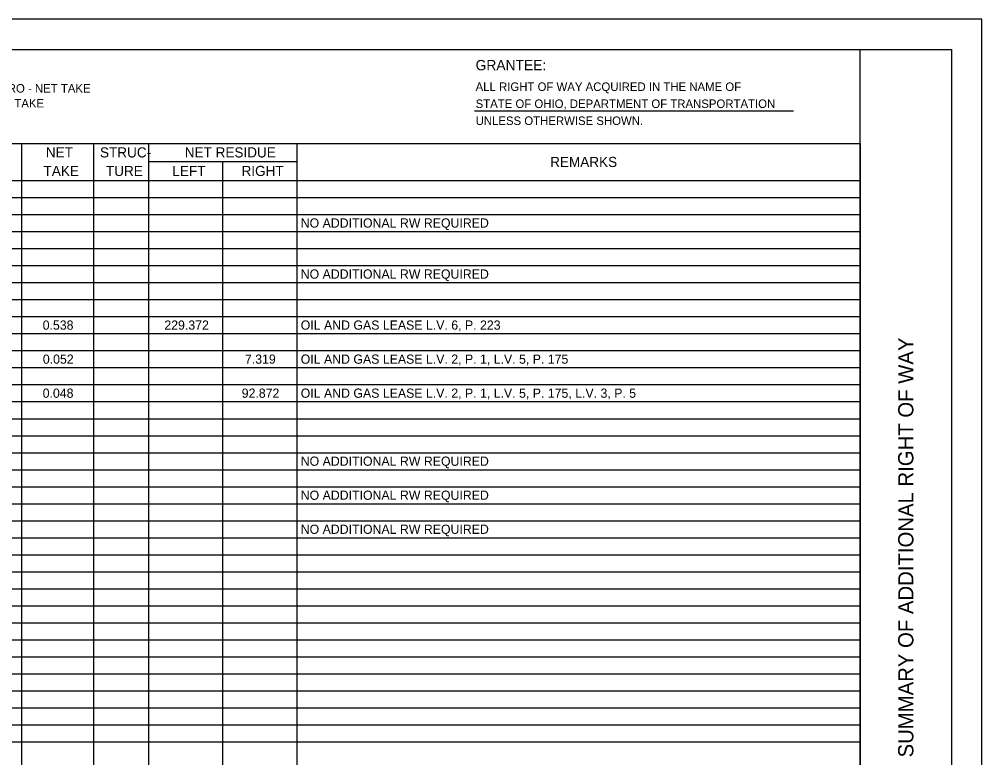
# Model space of a CAD drawing. Extents: x 0 to 34, y 0 to 22.
# Drawn here: x 18.16 to 34, y 9.85 to 22 of the extents above; entities that cross this region are included whole.
import ezdxf

# ---------------------------------------------------------------- set-up
doc = ezdxf.new("R2010")
doc.units = 0
for name, color, linetype in [('SH_Border', 7, 'Continuous'), ('SH_Cut_Line', 7, 'Continuous'), ('SH_Data', 7, 'Continuous'), ('SH_Text', 7, 'Continuous')]:
    doc.layers.add(name, color=color, linetype=linetype)

msp = doc.modelspace()

# ---------------------------------------------------------------- linework, layer by layer
at = {"layer": 'SH_Border'}
msp.add_line((32, 0.5), (32, 21.5), dxfattribs=at)
msp.add_lwpolyline([(1.5, 21.5), (33.5, 21.5), (33.5, 0.5), (1.5, 0.5)], close=True, dxfattribs=at)
at = {"layer": 'SH_Cut_Line'}
msp.add_lwpolyline([(0, 0), (34, 0), (34, 22), (0, 22)], close=True, dxfattribs=at)
at = {"layer": 'SH_Text'}
for p, q in [((25.651, 20.492), (30.9, 20.492)), ((1.5, 19.957), (32, 19.957)), ((18.199, 19.957), (18.199, 3.39)), ((19.385, 19.957), (19.385, 3.39)), ((20.291, 19.957), (20.291, 3.39)), ((22.728, 19.957), (22.728, 3.39)), ((32, 19.957), (32, 3.39)), ((20.291, 19.661), (22.728, 19.661)), ((21.509, 19.661), (21.509, 3.39)), ((1.5, 19.348), (32, 19.348)), ((1.5, 19.068), (32, 19.068)), ((1.5, 18.788), (32, 18.788)), ((1.5, 18.508), (32, 18.508)), ((1.5, 18.228), (32, 18.228)), ((1.5, 17.948), (32, 17.948)), ((1.5, 17.668), (32, 17.668)), ((1.5, 17.388), (32, 17.388)), ((1.5, 17.108), (32, 17.108)), ((1.5, 16.828), (32, 16.828)), ((1.5, 16.548), (32, 16.548)), ((1.5, 16.268), (32, 16.268)), ((1.5, 15.988), (32, 15.988)), ((1.5, 15.708), (32, 15.708)), ((1.5, 15.428), (32, 15.428)), ((1.5, 15.148), (32, 15.148)), ((1.5, 14.868), (32, 14.868)), ((1.5, 14.588), (32, 14.588)), ((1.5, 14.308), (32, 14.308)), ((1.5, 14.028), (32, 14.028)), ((1.5, 13.748), (32, 13.748)), ((1.5, 13.468), (32, 13.468)), ((1.5, 13.188), (32, 13.188)), ((1.5, 12.909), (32, 12.909)), ((1.5, 12.629), (32, 12.629)), ((1.5, 12.349), (32, 12.349)), ((1.5, 12.069), (32, 12.069)), ((1.5, 11.789), (32, 11.789)), ((1.5, 11.509), (32, 11.509)), ((1.5, 11.229), (32, 11.229)), ((1.5, 10.949), (32, 10.949)), ((1.5, 10.669), (32, 10.669)), ((1.5, 10.389), (32, 10.389)), ((1.5, 10.109), (32, 10.109))]:
    msp.add_line(p, q, dxfattribs=at)

# ---------------------------------------------------------------- texts
at = {"layer": 'SH_Data'}
msp.add_text('SUMMARY OF ADDITIONAL RIGHT OF WAY', height=0.25, rotation=90, dxfattribs=at).set_placement((32.875, 9.854))
at = {"layer": 'SH_Text'}
for s, height, p in [('GRANTEE:', 0.17, (25.672, 21.16)), ('NET RESIDUE = RECORD AREA - TOTAL PRO - NET TAKE', 0.14, (14.182, 20.793)), ('ALL RIGHT OF WAY ACQUIRED IN THE NAME OF', 0.14, (25.672, 20.82)), ('NET TAKE = GROSS TAKE - PRO IN TAKE', 0.14, (14.873, 20.548)), ('STATE OF OHIO, DEPARTMENT OF TRANSPORTATION', 0.14, (25.672, 20.54)), ('UNLESS OTHERWISE SHOWN.', 0.14, (25.672, 20.26)), ('NET', 0.1667, (18.601, 19.726)), ('STRUC-', 0.1667, (19.491, 19.726)), ('NET RESIDUE', 0.16666, (20.886, 19.726)), ('REMARKS', 0.1667, (26.898, 19.569)), ('TAKE', 0.1667, (18.562, 19.421)), ('TURE', 0.1667, (19.589, 19.421)), ('LEFT', 0.1667, (20.682, 19.421)), ('RIGHT', 0.1667, (21.82, 19.421)), ('NO ADDITIONAL RW REQUIRED', 0.15151, (22.794, 18.572)), ('NO ADDITIONAL RW REQUIRED', 0.15151, (22.794, 17.732)), ('0.538', 0.1515, (18.548, 16.892)), ('229.372', 0.1515, (20.55, 16.892)), ('OIL AND GAS LEASE L.V. 6, P. 223', 0.15151, (22.794, 16.892)), ('0.052', 0.1515, (18.551, 16.332)), ('7.319', 0.1515, (21.876, 16.332)), ('OIL AND GAS LEASE L.V. 2, P. 1, L.V. 5, P. 175', 0.15151, (22.794, 16.332)), ('0.048', 0.1515, (18.548, 15.772)), ('92.872', 0.1515, (21.823, 15.772)), ('OIL AND GAS LEASE L.V. 2, P. 1, L.V. 5, P. 175, L.V. 3, P. 5', 0.15151, (22.794, 15.772)), ('NO ADDITIONAL RW REQUIRED', 0.15151, (22.794, 14.653)), ('NO ADDITIONAL RW REQUIRED', 0.15151, (22.794, 14.093)), ('NO ADDITIONAL RW REQUIRED', 0.15151, (22.794, 13.533))]:
    msp.add_text(s, height=height, dxfattribs=at).set_placement(p)

doc.saveas('drawing.dxf')
